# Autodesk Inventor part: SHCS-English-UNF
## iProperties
Author: Neil Munro -Ron Crain
Shininess: 48.0
PropertySet Name: _Private Model Information
Created: 2001-02
Part Number: SHCS-English-UNF
Material: Steel, High Strength Low Alloy
Document SubType Name: Modeling
Designer: Administrator
Control State: 0
Master: False
Checked Out: False
PropertySet Name: Design Tracking Control
Density: 7.84
Volumn: 1.169971795574453
Area: 8.616428999425011
PropertySet Name: Model Information
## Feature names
1. Body [Extrusion]
2. Head [Extrusion]
3. Hex [Extrusion]
4. Chamfer1
